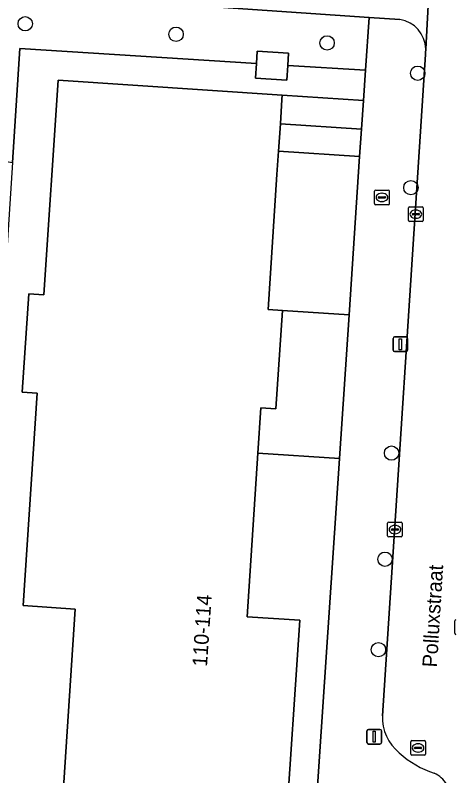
# Model space of a CAD drawing. Extents: x 161848 to 162726, y 385382 to 386521.
# Drawn here: x 161919.8 to 161949.7, y 385526.1 to 385578 of the extents above; entities that cross this region are included whole.
import ezdxf

# ---------------------------------------------------------------- set-up
doc = ezdxf.new("R2010")
doc.units = 0
for name, color, linetype in [('IMGEO_Boom', 7, 'Continuous'), ('IMGEO_Brandkraan', 7, 'Continuous'), ('IMGEO_Fietspad_open', 7, 'Continuous'), ('IMGEO_Groenvoorziening', 7, 'Continuous'), ('IMGEO_Kolk', 7, 'Continuous'), ('IMGEO_Lage_trafo', 7, 'Continuous'), ('IMGEO_Lichtmast', 7, 'Continuous'), ('IMGEO_Loofbos', 7, 'Continuous'), ('IMGEO_Openbare_ruimte_label', 7, 'Continuous'), ('IMGEO_Pand', 7, 'Continuous'), ('IMGEO_Pand_nummerreeks', 7, 'Continuous'), ('IMGEO_Rijbaan_lokaal_open', 7, 'Continuous'), ('IMGEO_Rioolput', 7, 'Continuous'), ('IMGEO_Voetpad_open', 7, 'Continuous')]:
    doc.layers.add(name, color=color, linetype=linetype)

msp = doc.modelspace()

# ---------------------------------------------------------------- linework, layer by layer
at = {"layer": 'IMGEO_Boom'}
for centre in [(161920.489, 385577.372), (161930.76, 385576.655), (161941.043, 385576.064), (161947.214, 385574), (161946.748, 385566.198), (161945.43, 385548.109), (161944.983, 385540.877), (161944.539, 385534.71)]:
    msp.add_circle(centre, 0.489, dxfattribs=at)
at = {"layer": 'IMGEO_Brandkraan'}
for p, q in [((161944.28, 385565.111), (161944.28, 385565.963)), ((161944.355, 385566.037), (161945.207, 385566.037)), ((161945.281, 385565.963), (161945.281, 385565.111)), ((161944.539, 385565.531), (161944.539, 385565.543)), ((161944.977, 385565.494), (161944.579, 385565.494)), ((161944.582, 385565.58), (161944.98, 385565.58)), ((161944.768, 385565.817), (161944.793, 385565.817)), ((161945.023, 385565.543), (161945.023, 385565.531)), ((161945.207, 385565.037), (161944.355, 385565.037)), ((161944.791, 385565.257), (161944.766, 385565.257))]:
    msp.add_line(p, q, dxfattribs=at)
for points in [[(161944.28, 385565.111), (161944.28, 385565.963)], [(161944.355, 385566.037), (161945.207, 385566.037)], [(161945.281, 385565.963), (161945.281, 385565.111)], [(161945.207, 385565.037), (161944.355, 385565.037)]]:
    msp.add_lwpolyline(points, dxfattribs=at)
for centre, radius, start, end in [((161944.357, 385565.961), 0.0765, 91.552, 178.448), ((161944.357, 385565.961), 0.0765, 91.552, 178.448), ((161945.205, 385565.961), 0.0765, 1.552, 88.448), ((161945.205, 385565.961), 0.0765, 1.552, 88.448), ((161944.579, 385565.54), 0.0403, 85.8775, 175.7526), ((161944.576, 385565.53), 0.0366, 178.938, 274.7102), ((161944.98, 385565.537), 0.043, 264.8664, 352.4533), ((161944.984, 385565.542), 0.0386, 1.7309, 96.639), ((161944.357, 385565.113), 0.0765, 181.552, 268.448), ((161944.357, 385565.113), 0.0765, 181.552, 268.448), ((161945.205, 385565.113), 0.0765, 271.552, 358.448), ((161945.205, 385565.113), 0.0765, 271.552, 358.448)]:
    msp.add_arc(centre, radius, start, end, dxfattribs=at)
for centre, major_axis, ratio, start_param, end_param in [((161944.767, 385565.537), (-0.387, 0.002), 0.722429, 4.712389, 7.853982), ((161944.792, 385565.537), (-0.39, 0.002), 0.717154, 1.570796, 4.712389)]:
    msp.add_ellipse(centre, major_axis=major_axis, ratio=ratio, start_param=start_param, end_param=end_param, dxfattribs=at)
at = {"layer": 'IMGEO_Fietspad_open'}
for points in [[(161947.765, 385575.649), (161948.085, 385581.619)], [(161898.755, 385580.924), (161908.162, 385580.274), (161943.897, 385577.803), (161945.997, 385577.661)]]:
    msp.add_lwpolyline(points, dxfattribs=at)
msp.add_arc((161945.659, 385575.581), 2.107, 1.837, 80.7764, dxfattribs=at)
at = {"layer": 'IMGEO_Groenvoorziening'}
for points in [[(161938.367, 385574.532), (161943.654, 385574.199), (161943.897, 385577.803), (161908.162, 385580.274), (161907.621, 385569.927), (161914.879, 385568.706), (161919.62, 385567.908), (161920.123, 385575.681), (161936.231, 385574.667), (161936.287, 385575.511), (161938.423, 385575.37)], [(161943.515, 385572.144), (161937.991, 385572.511), (161937.971, 385572.208), (161937.861, 385570.546), (161943.383, 385570.18)], [(161943.258, 385568.315), (161937.737, 385568.681), (161937.632, 385567.089), (161937.023, 385557.9), (161937.996, 385557.835), (161942.536, 385557.531)], [(161941.881, 385547.741), (161936.339, 385548.108), (161935.601, 385536.955), (161939.183, 385536.718), (161938.221, 385522.178), (161939.194, 385522.114), (161938.747, 385515.366), (161937.764, 385515.432), (161936.796, 385500.803), (161938.731, 385500.698)]]:
    msp.add_lwpolyline(points, close=True, dxfattribs=at)
at = {"layer": 'IMGEO_Kolk'}
for p, q in [((161946.586, 385563.965), (161946.586, 385564.817)), ((161946.661, 385564.891), (161947.513, 385564.891)), ((161946.845, 385564.385), (161946.845, 385564.397)), ((161946.888, 385564.434), (161947.286, 385564.434)), ((161947.074, 385564.671), (161947.099, 385564.671)), ((161947.329, 385564.397), (161947.329, 385564.385)), ((161947.587, 385564.817), (161947.587, 385563.965)), ((161947.513, 385563.891), (161946.661, 385563.891)), ((161947.283, 385564.348), (161946.885, 385564.348)), ((161947.097, 385564.111), (161947.072, 385564.111)), ((161945.164, 385542.471), (161945.164, 385543.323)), ((161945.239, 385543.397), (161946.091, 385543.397)), ((161945.652, 385543.177), (161945.677, 385543.177)), ((161946.165, 385543.323), (161946.165, 385542.471)), ((161945.423, 385542.891), (161945.423, 385542.903)), ((161945.861, 385542.854), (161945.463, 385542.854)), ((161945.466, 385542.94), (161945.864, 385542.94)), ((161945.907, 385542.903), (161945.907, 385542.891)), ((161946.091, 385542.397), (161945.239, 385542.397)), ((161945.675, 385542.617), (161945.65, 385542.617)), ((161949.736, 385535.828), (161949.736, 385536.68))]:
    msp.add_line(p, q, dxfattribs=at)
for points in [[(161946.586, 385563.965), (161946.586, 385564.817)], [(161946.661, 385564.891), (161947.513, 385564.891)], [(161947.587, 385564.817), (161947.587, 385563.965)], [(161947.513, 385563.891), (161946.661, 385563.891)], [(161945.164, 385542.471), (161945.164, 385543.323)], [(161945.239, 385543.397), (161946.091, 385543.397)], [(161946.165, 385543.323), (161946.165, 385542.471)], [(161946.091, 385542.397), (161945.239, 385542.397)], [(161949.736, 385535.828), (161949.736, 385536.68)]]:
    msp.add_lwpolyline(points, dxfattribs=at)
for centre, radius, start, end in [((161946.663, 385564.815), 0.0765, 91.552, 178.448), ((161946.663, 385564.815), 0.0765, 91.552, 178.448), ((161946.885, 385564.394), 0.0403, 85.8775, 175.7526), ((161947.29, 385564.396), 0.0386, 1.7309, 96.639), ((161947.511, 385564.815), 0.0765, 1.552, 88.448), ((161947.511, 385564.815), 0.0765, 1.552, 88.448), ((161946.663, 385563.967), 0.0765, 181.552, 268.448), ((161946.663, 385563.967), 0.0765, 181.552, 268.448), ((161946.882, 385564.384), 0.0366, 178.938, 274.7102), ((161947.286, 385564.391), 0.043, 264.8664, 352.4533), ((161947.511, 385563.967), 0.0765, 271.552, 358.448), ((161947.511, 385563.967), 0.0765, 271.552, 358.448), ((161945.241, 385543.321), 0.0765, 91.552, 178.448), ((161945.241, 385543.321), 0.0765, 91.552, 178.448), ((161946.089, 385543.321), 0.0765, 1.552, 88.448), ((161946.089, 385543.321), 0.0765, 1.552, 88.448), ((161945.463, 385542.9), 0.0403, 85.8775, 175.7526), ((161945.46, 385542.89), 0.0366, 178.938, 274.7102), ((161945.864, 385542.897), 0.043, 264.8664, 352.4533), ((161945.868, 385542.902), 0.0386, 1.7309, 96.639), ((161945.241, 385542.473), 0.0765, 181.552, 268.448), ((161945.241, 385542.473), 0.0765, 181.552, 268.448), ((161946.089, 385542.473), 0.0765, 271.552, 358.448), ((161946.089, 385542.473), 0.0765, 271.552, 358.448), ((161949.813, 385536.678), 0.0765, 91.552, 178.448), ((161949.813, 385536.678), 0.0765, 91.552, 178.448), ((161949.813, 385535.83), 0.0765, 181.552, 268.448), ((161949.813, 385535.83), 0.0765, 181.552, 268.448)]:
    msp.add_arc(centre, radius, start, end, dxfattribs=at)
for centre, major_axis, ratio, start_param, end_param in [((161947.073, 385564.391), (-0.387, 0.002), 0.722429, 4.712389, 7.853982), ((161947.098, 385564.391), (-0.39, 0.002), 0.717154, 1.570796, 4.712389), ((161945.651, 385542.897), (-0.387, 0.002), 0.722429, 4.712389, 7.853982), ((161945.676, 385542.897), (-0.39, 0.002), 0.717154, 1.570796, 4.712389)]:
    msp.add_ellipse(centre, major_axis=major_axis, ratio=ratio, start_param=start_param, end_param=end_param, dxfattribs=at)
at = {"layer": 'IMGEO_Lage_trafo'}
msp.add_lwpolyline([(161938.423, 385575.37), (161936.287, 385575.511), (161936.231, 385574.667), (161936.164, 385573.665), (161938.3, 385573.524), (161938.367, 385574.532)], close=True, dxfattribs=at)
at = {"layer": 'IMGEO_Lichtmast'}
for p, q in [((161945.534, 385555.129), (161945.534, 385555.929)), ((161945.534, 385555.929), (161945.534, 385555.129)), ((161945.634, 385556.029), (161946.424, 385556.029)), ((161946.424, 385556.029), (161945.634, 385556.029)), ((161946.524, 385555.929), (161946.524, 385555.129)), ((161946.524, 385555.129), (161946.524, 385555.929)), ((161946.424, 385555.029), (161945.634, 385555.029)), ((161945.634, 385555.029), (161946.424, 385555.029)), ((161943.754, 385528.379), (161943.754, 385529.179)), ((161943.754, 385529.179), (161943.754, 385528.379)), ((161943.854, 385529.279), (161944.644, 385529.279)), ((161944.644, 385529.279), (161943.854, 385529.279)), ((161944.744, 385529.179), (161944.744, 385528.379)), ((161944.744, 385528.379), (161944.744, 385529.179)), ((161944.644, 385528.279), (161943.854, 385528.279)), ((161943.854, 385528.279), (161944.644, 385528.279))]:
    msp.add_line(p, q, dxfattribs=at)
for points in [[(161945.954, 385555.904), (161946.104, 385555.904), (161946.104, 385555.154), (161945.954, 385555.154), (161945.954, 385555.904)], [(161944.174, 385529.154), (161944.324, 385529.154), (161944.324, 385528.404), (161944.174, 385528.404), (161944.174, 385529.154)]]:
    msp.add_lwpolyline(points, dxfattribs=at)
for centre, start, end in [((161945.634, 385555.929), 90, 180), ((161945.634, 385555.929), 90, 180), ((161946.424, 385555.929), 0, 90), ((161946.424, 385555.929), 360, 90), ((161945.634, 385555.129), 180, 270), ((161945.634, 385555.129), 180, 270), ((161946.424, 385555.129), 270, 0), ((161946.424, 385555.129), 270, 0), ((161943.854, 385529.179), 90, 180), ((161943.854, 385529.179), 90, 180), ((161944.644, 385529.179), 0, 90), ((161944.644, 385529.179), 360, 90), ((161943.854, 385528.379), 180, 270), ((161943.854, 385528.379), 180, 270), ((161944.644, 385528.379), 270, 0), ((161944.644, 385528.379), 270, 0)]:
    msp.add_arc(centre, 0.1, start, end, dxfattribs=at)
at = {"layer": 'IMGEO_Loofbos'}
msp.add_lwpolyline([(161937.991, 385572.511), (161943.515, 385572.144), (161943.654, 385574.199), (161938.367, 385574.532), (161938.3, 385573.524), (161936.164, 385573.665), (161936.231, 385574.667), (161920.123, 385575.681), (161919.62, 385567.908), (161915.33, 385501.593), (161920.322, 385501.259), (161921.48, 385501.182), (161921.522, 385501.814), (161922.49, 385516.433), (161921.491, 385516.499), (161921.941, 385523.3), (161922.958, 385523.233), (161923.902, 385537.482), (161920.343, 385537.718), (161921.301, 385552.184), (161920.286, 385552.252), (161920.73, 385558.966), (161921.757, 385558.898), (161922.725, 385573.521)], close=True, dxfattribs=at)
at = {"layer": 'IMGEO_Pand'}
msp.add_lwpolyline([(161938.221, 385522.178), (161939.183, 385536.718), (161935.601, 385536.955), (161936.339, 385548.108), (161936.543, 385551.193), (161937.552, 385551.126), (161937.996, 385557.835), (161937.023, 385557.9), (161937.632, 385567.089), (161937.737, 385568.681), (161937.861, 385570.546), (161937.971, 385572.208), (161937.991, 385572.511), (161922.725, 385573.521), (161921.757, 385558.898), (161920.73, 385558.966), (161920.286, 385552.252), (161921.301, 385552.184), (161920.343, 385537.718), (161923.902, 385537.482), (161922.958, 385523.233)], dxfattribs=at)
at = {"layer": 'IMGEO_Rijbaan_lokaal_open'}
msp.add_lwpolyline([(161958.177, 385576.956), (161994.035, 385574.544), (161996.279, 385574.381), (161996.609, 385579.459), (161993.817, 385579.653), (161948.87, 385582.767), (161948.39, 385582.793), (161948.085, 385581.619), (161947.765, 385575.649), (161947.75, 385575.399), (161947.742, 385575.268), (161944.809, 385530.214)], dxfattribs=at)
for centre, radius, start, end in [((161947.953, 385530.109), 3.146, 178.0804, 230.7123), ((161950.227, 385532.297), 6.29, 227.2962, 252.542), ((161947.634, 385524.681), 1.763, 29.0633, 66.3962)]:
    msp.add_arc(centre, radius, start, end, dxfattribs=at)
at = {"layer": 'IMGEO_Rioolput'}
for p, q in [((161946.737, 385527.588), (161946.737, 385528.44)), ((161946.812, 385528.514), (161947.664, 385528.514)), ((161947.225, 385528.294), (161947.25, 385528.294)), ((161947.738, 385528.44), (161947.738, 385527.588)), ((161946.996, 385528.008), (161946.996, 385528.02)), ((161947.434, 385527.971), (161947.036, 385527.971)), ((161947.039, 385528.057), (161947.437, 385528.057)), ((161947.248, 385527.734), (161947.223, 385527.734)), ((161947.48, 385528.02), (161947.48, 385528.008)), ((161947.664, 385527.514), (161946.812, 385527.514))]:
    msp.add_line(p, q, dxfattribs=at)
for points in [[(161946.737, 385527.588), (161946.737, 385528.44)], [(161946.812, 385528.514), (161947.664, 385528.514)], [(161947.738, 385528.44), (161947.738, 385527.588)], [(161947.664, 385527.514), (161946.812, 385527.514)]]:
    msp.add_lwpolyline(points, dxfattribs=at)
for centre, radius, start, end in [((161946.814, 385528.438), 0.0765, 91.552, 178.448), ((161946.814, 385528.438), 0.0765, 91.552, 178.448), ((161947.662, 385528.438), 0.0765, 1.552, 88.448), ((161947.662, 385528.438), 0.0765, 1.552, 88.448), ((161946.814, 385527.59), 0.0765, 181.552, 268.448), ((161946.814, 385527.59), 0.0765, 181.552, 268.448), ((161947.036, 385528.017), 0.0403, 85.8775, 175.7526), ((161947.033, 385528.007), 0.0366, 178.938, 274.7102), ((161947.437, 385528.014), 0.043, 264.8664, 352.4533), ((161947.441, 385528.019), 0.0386, 1.7309, 96.639), ((161947.662, 385527.59), 0.0765, 271.552, 358.448), ((161947.662, 385527.59), 0.0765, 271.552, 358.448)]:
    msp.add_arc(centre, radius, start, end, dxfattribs=at)
for centre, major_axis, ratio, start_param, end_param in [((161947.224, 385528.014), (-0.387, 0.002), 0.722429, 4.712389, 7.853982), ((161947.249, 385528.014), (-0.39, 0.002), 0.717154, 1.570796, 4.712389)]:
    msp.add_ellipse(centre, major_axis=major_axis, ratio=ratio, start_param=start_param, end_param=end_param, dxfattribs=at)
at = {"layer": 'IMGEO_Voetpad_open'}
for points in [[(161945.997, 385577.661), (161943.897, 385577.803), (161943.654, 385574.199), (161943.515, 385572.144), (161943.383, 385570.18), (161943.258, 385568.315), (161942.536, 385557.531), (161941.881, 385547.741), (161938.731, 385500.698)], [(161944.809, 385530.214), (161947.742, 385575.268), (161947.75, 385575.399), (161947.765, 385575.649)]]:
    msp.add_lwpolyline(points, dxfattribs=at)
for points in [[(161943.383, 385570.18), (161937.861, 385570.546), (161937.737, 385568.681), (161943.258, 385568.315)], [(161942.536, 385557.531), (161937.996, 385557.835), (161937.552, 385551.126), (161936.543, 385551.193), (161936.339, 385548.108), (161941.881, 385547.741)]]:
    msp.add_lwpolyline(points, close=True, dxfattribs=at)
for centre, radius, start, end in [((161945.659, 385575.581), 2.107, 1.837, 80.7764), ((161947.953, 385530.109), 3.146, 178.0804, 230.7123), ((161950.227, 385532.297), 6.29, 227.2962, 252.542), ((161947.634, 385524.681), 1.763, 29.0633, 66.3962)]:
    msp.add_arc(centre, radius, start, end, dxfattribs=at)

# ---------------------------------------------------------------- texts
at = {"layer": 'IMGEO_Openbare_ruimte_label'}
msp.add_text('Polluxstraat', height=1, rotation=86.5023, dxfattribs=at).set_placement((161948.522, 385533.487))
at = {"layer": 'IMGEO_Pand_nummerreeks'}
msp.add_text('110-114', height=1, rotation=86.1843, dxfattribs=at).set_placement((161932.865, 385533.535))

doc.saveas('drawing.dxf')
